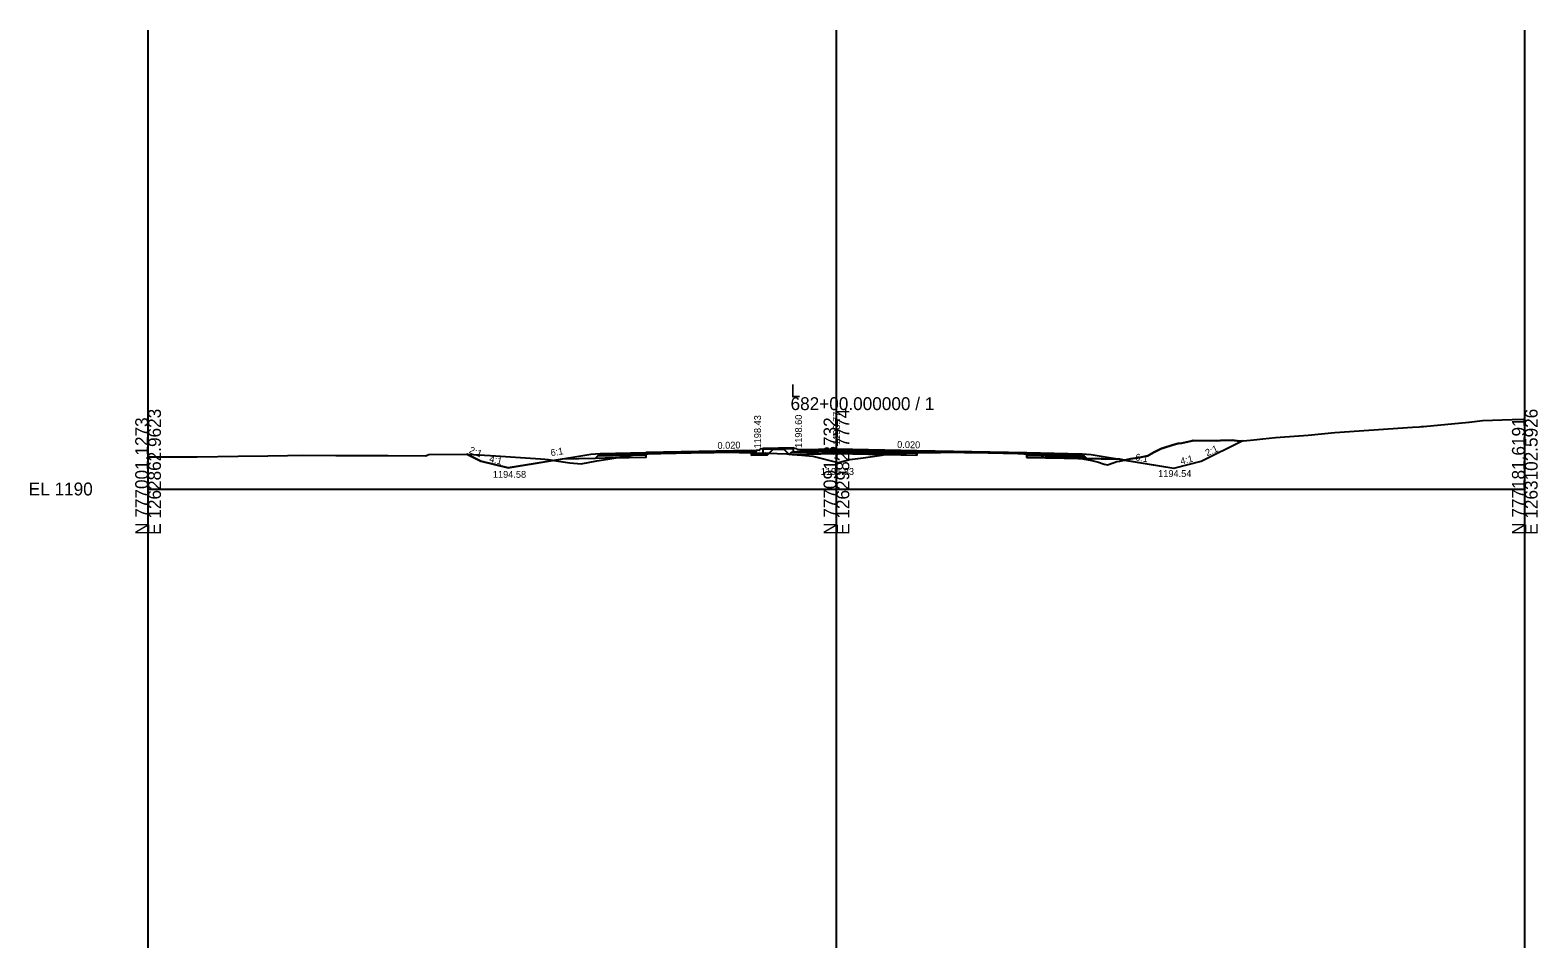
# Model space of a CAD drawing. Extents: x -41 to 1262860, y -100 to 777489.
# Drawn here: x 474.3 to 802.8, y 4065 to 4265 of the extents above; entities that cross this region are included whole.
import ezdxf

# ---------------------------------------------------------------- set-up
doc = ezdxf.new("R2010")
doc.units = 0
for name, color, linetype in [('Exist Cross Section Cell', 7, 'Continuous'), ('Exist XS Center Line Elevation Label', 7, 'Continuous'), ('Exist XS Ground Line', 7, 'Continuous'), ('Prop CMT Pvmt Course 1', 7, 'Continuous'), ('Prop CMT Pvmt Surface', 7, 'Continuous'), ('Prop CMT Shld Paved Course 1', 7, 'Continuous'), ('Prop CMT Shld Paved Course 2', 7, 'Continuous'), ('Prop CMT Shld Paved Course 4', 7, 'Continuous'), ('Prop CMT Subgrade Earthwork', 7, 'Continuous'), ('Prop Conc Curb and Gutter', 7, 'Continuous'), ('Prop Conc Island Cover', 7, 'Continuous'), ('Prop XS Ditch Standard Text', 7, 'Continuous'), ('Prop XS Earthwork Shape', 7, 'Continuous'), ('Prop XS Elevation Labels', 7, 'Continuous'), ('Prop XS Exc Vertical Line 1', 7, 'Continuous'), ('Prop XS Exc Vertical Line 2', 7, 'Continuous'), ('Prop XS Exc Vertical Line 3', 7, 'Continuous'), ('Prop XS Finish Grade', 7, 'Continuous'), ('Prop XS Hydro Elevations', 7, 'Continuous'), ('Prop XS SE Text', 7, 'Continuous'), ('Prop XS Side Slope Text', 7, 'Continuous'), ('Scratch_Level_4', 7, 'Continuous'), ('Scratch_Level_6', 7, 'Continuous')]:
    doc.layers.add(name, color=color, linetype=linetype)

msp = doc.modelspace()

# ---------------------------------------------------------------- linework, layer by layer
at = {"layer": 'Exist Cross Section Cell'}
for p, q in [((650, 4165), (650, 4185)), ((500, 4165), (650, 4165)), ((650, 4165), (800, 4165))]:
    msp.add_line(p, q, dxfattribs=at)
at = {"layer": 'Exist XS Ground Line'}
msp.add_lwpolyline([(500, 4172.04), (509.52, 4172.01), (510.05, 4172.01), (510.31, 4172.01), (510.7, 4172.02), (519.64, 4172.14), (526.09, 4172.23), (530.37, 4172.31), (533.6, 4172.34), (540.9, 4172.31), (551.94, 4172.31), (552.3, 4172.31), (560.54, 4172.22), (560.84, 4172.37), (561.2, 4172.55), (569.48, 4172.61), (569.78, 4172.6), (575.68, 4172.22), (585.55, 4171.57), (586.44, 4171.52), (587.2, 4171.4), (591.88, 4170.72), (594.34, 4170.49), (594.37, 4170.49), (594.39, 4170.49), (597.79, 4171.11), (600.18, 4171.51), (603.32, 4172.02), (603.77, 4172.09), (607.39, 4172.64), (608.94, 4172.75), (610.76, 4172.87), (617.6, 4172.95), (623.39, 4173.02), (628.79, 4172.93), (635.33, 4172.8), (637.07, 4172.72), (639.18, 4172.63), (642.49, 4172.36), (644.87, 4172.12), (650.29, 4170.76), (650.37, 4170.74), (650.42, 4170.75), (652.92, 4171.45), (655.81, 4171.81), (659.86, 4172.38), (661.46, 4172.63), (664.64, 4172.79), (665.3, 4172.82), (667.47, 4172.85), (677.88, 4173.02), (679.87, 4172.98), (689.55, 4172.78), (691.46, 4172.61), (692.25, 4172.52), (693.7, 4172.39), (698.26, 4172.02), (699.68, 4171.9), (703.23, 4171.63), (705.66, 4171.18), (707.1, 4170.84), (708.37, 4170.44), (709.04, 4170.24), (710.49, 4170.75), (711.1, 4170.97), (711.75, 4171.09), (714.07, 4171.6), (715.65, 4171.77), (717.85, 4172.24), (719.1, 4172.94), (720.85, 4173.84), (721.13, 4173.89), (723.35, 4174.65), (724.47, 4174.88), (725.27, 4175.01), (727.52, 4175.5), (727.74, 4175.54), (732.76, 4175.51), (733.72, 4175.58), (736.22, 4175.64), (737.82, 4175.46), (738.65, 4175.51), (740.26, 4175.65), (741.64, 4175.81), (742.9, 4175.95), (745.67, 4176.19), (752.8, 4176.72), (758.6, 4177.3), (775.54, 4178.47), (777.02, 4178.57), (777.52, 4178.59), (777.94, 4178.61), (787.78, 4179.58), (787.89, 4179.59), (790.75, 4179.94), (797.25, 4180.13), (800, 4180.24)], dxfattribs=at)
at = {"layer": 'Prop CMT Pvmt Course 1'}
for p, q in [((631.5, 4173.15), (632.5, 4173.17)), ((632.5, 4173.42), (632.5, 4173.17)), ((642.16, 4173.61), (642.16, 4173.36))]:
    msp.add_line(p, q, dxfattribs=at)
for points in [[(608.5, 4172.94), (608.5, 4172.69), (631.5, 4173.15), (631.5, 4173.15), (631.5, 4173.4), (631.5, 4173.4), (631.5, 4173.4), (608.5, 4172.94), (608.5, 4172.94)], [(642.16, 4173.36), (650, 4173.52), (667.5, 4173.17)], [(691.5, 4172.94), (691.5, 4172.69), (691.5, 4172.69), (667.5, 4173.17), (667.5, 4173.17), (667.5, 4173.42), (667.5, 4173.42), (667.5, 4173.42), (691.5, 4172.94), (691.5, 4172.94), (691.5, 4172.94)]]:
    msp.add_lwpolyline(points, dxfattribs=at)
at = {"layer": 'Prop CMT Pvmt Surface'}
for p, q in [((598.5, 4172.74), (608.5, 4172.94)), ((608.5, 4172.94), (631.5, 4173.4)), ((631.5, 4173.4), (632.5, 4173.42)), ((667.5, 4173.42), (691.5, 4172.94)), ((691.5, 4172.94), (703.5, 4172.7))]:
    msp.add_line(p, q, dxfattribs=at)
msp.add_lwpolyline([(642.16, 4173.61), (650, 4173.77), (667.5, 4173.42)], dxfattribs=at)
at = {"layer": 'Prop CMT Shld Paved Course 1'}
for p, q in [((598.24, 4172.48), (598.5, 4172.74)), ((608.5, 4172.69), (598.24, 4172.48)), ((604.5, 4172.86), (604.5, 4172.86)), ((608.5, 4172.94), (608.5, 4172.94)), ((608.5, 4172.94), (608.5, 4172.94)), ((608.5, 4172.94), (608.5, 4172.69)), ((608.5, 4172.69), (608.5, 4172.69)), ((691.5, 4172.94), (691.5, 4172.94)), ((691.5, 4172.94), (691.5, 4172.94)), ((691.5, 4172.94), (691.5, 4172.69)), ((691.5, 4172.69), (691.5, 4172.69)), ((691.5, 4172.69), (703.76, 4172.44)), ((695.5, 4172.86), (695.5, 4172.86)), ((703.76, 4172.44), (703.5, 4172.7))]:
    msp.add_line(p, q, dxfattribs=at)
at = {"layer": 'Prop CMT Shld Paved Course 2'}
for p, q in [((597.9, 4172.14), (598.24, 4172.48)), ((604.24, 4172.6), (604.24, 4172.6)), ((608.5, 4172.69), (608.5, 4172.69)), ((608.5, 4172.69), (608.5, 4172.69)), ((608.5, 4172.69), (608.5, 4172.35)), ((608.5, 4172.69), (608.94, 4172.69)), ((608.94, 4172.69), (608.5, 4172.69)), ((608.94, 4172.69), (610.76, 4172.73)), ((610.76, 4172.73), (608.94, 4172.69)), ((608.94, 4172.69), (608.94, 4172.69)), ((608.94, 4172.69), (608.94, 4172.69)), ((610.76, 4172.73), (617.6, 4172.87)), ((617.6, 4172.87), (610.76, 4172.73)), ((610.76, 4172.73), (610.76, 4172.73)), ((610.76, 4172.73), (610.76, 4172.73)), ((610.76, 4172.73), (610.76, 4172.73)), ((610.76, 4172.73), (610.76, 4172.73)), ((617.6, 4172.87), (623.39, 4172.98)), ((623.39, 4172.98), (617.6, 4172.87)), ((617.6, 4172.87), (617.6, 4172.87)), ((617.6, 4172.87), (617.6, 4172.87)), ((628.79, 4173.09), (623.39, 4172.98)), ((623.39, 4172.98), (624.26, 4173)), ((623.39, 4172.98), (623.39, 4172.98)), ((624.26, 4173), (628.79, 4172.93)), ((631.5, 4173.15), (628.79, 4173.09)), ((628.79, 4173.09), (628.79, 4173.09)), ((628.79, 4172.93), (628.79, 4172.93)), ((628.79, 4172.93), (631.5, 4172.87)), ((631.5, 4172.87), (631.5, 4173.15)), ((631.5, 4173.15), (631.5, 4173.15)), ((631.5, 4172.87), (631.5, 4172.81)), ((631.5, 4172.81), (632.5, 4172.83)), ((632.5, 4172.83), (632.5, 4173.17)), ((642.16, 4173.03), (642.16, 4173.36)), ((667.5, 4172.85), (667.5, 4173.17)), ((667.5, 4173.17), (667.5, 4173.17)), ((667.5, 4173.17), (667.5, 4173.17)), ((667.5, 4173.17), (677.88, 4172.96)), ((676.08, 4172.99), (667.5, 4172.85)), ((667.5, 4172.85), (667.5, 4172.83)), ((667.5, 4172.85), (667.5, 4172.85)), ((677.88, 4172.96), (676.08, 4172.99)), ((676.08, 4172.99), (676.08, 4172.99)), ((676.08, 4172.99), (676.08, 4172.99)), ((679.87, 4172.92), (677.88, 4172.96)), ((677.88, 4172.96), (677.88, 4172.96)), ((677.88, 4172.96), (679.87, 4172.92)), ((689.55, 4172.72), (679.87, 4172.92)), ((679.87, 4172.92), (679.87, 4172.92)), ((679.87, 4172.92), (679.87, 4172.92)), ((679.87, 4172.92), (679.87, 4172.92)), ((679.87, 4172.92), (679.87, 4172.92)), ((679.87, 4172.92), (679.87, 4172.92)), ((679.87, 4172.92), (679.87, 4172.92)), ((679.87, 4172.92), (689.55, 4172.72)), ((690.37, 4172.71), (689.55, 4172.72)), ((689.55, 4172.72), (689.55, 4172.72)), ((689.55, 4172.72), (689.55, 4172.72)), ((689.55, 4172.72), (689.55, 4172.72)), ((689.55, 4172.72), (689.55, 4172.72)), ((689.55, 4172.72), (691.46, 4172.69)), ((691.46, 4172.61), (690.37, 4172.71)), ((690.37, 4172.71), (690.37, 4172.71)), ((690.37, 4172.71), (690.37, 4172.71)), ((691.46, 4172.69), (691.5, 4172.69)), ((691.46, 4172.69), (691.46, 4172.69)), ((691.5, 4172.6), (691.46, 4172.61)), ((691.5, 4172.69), (691.5, 4172.69)), ((691.5, 4172.69), (691.5, 4172.69)), ((691.5, 4172.69), (691.5, 4172.35)), ((691.5, 4172.69), (691.5, 4172.69)), ((691.5, 4172.69), (691.5, 4172.6)), ((704.1, 4172.1), (703.76, 4172.44)), ((608.5, 4172.35), (597.9, 4172.14)), ((608.5, 4172.35), (608.5, 4172.35)), ((691.5, 4172.35), (691.5, 4172.35)), ((691.5, 4172.35), (704.1, 4172.1))]:
    msp.add_line(p, q, dxfattribs=at)
msp.add_lwpolyline([(642.16, 4173.03), (650, 4173.18), (667.5, 4172.83)], dxfattribs=at)
at = {"layer": 'Prop CMT Shld Paved Course 4'}
for p, q in [((631.5, 4172.81), (631.5, 4172.35)), ((631.5, 4172.35), (634.95, 4172.42)), ((632.5, 4172.83), (634.5, 4172.87)), ((634.5, 4172.87), (634.95, 4172.42)), ((640.16, 4172.99), (639.69, 4172.52)), ((642.16, 4172.57), (639.69, 4172.52)), ((642.16, 4173.03), (640.16, 4172.99)), ((667.5, 4172.83), (667.5, 4172.37)), ((597.44, 4171.67), (597.9, 4172.14)), ((608.5, 4171.89), (597.44, 4171.67)), ((603.4, 4172.25), (603.4, 4172.25)), ((603.9, 4172.26), (603.9, 4172.26)), ((608.5, 4172.35), (608.5, 4172.35)), ((608.5, 4172.35), (608.5, 4172.35)), ((608.5, 4172.35), (608.5, 4171.89)), ((691.5, 4172.35), (691.5, 4172.35)), ((691.5, 4172.35), (691.5, 4172.35)), ((691.5, 4172.35), (691.5, 4171.89)), ((691.5, 4171.89), (704.56, 4171.63)), ((704.56, 4171.63), (704.1, 4172.1))]:
    msp.add_line(p, q, dxfattribs=at)
msp.add_lwpolyline([(642.16, 4172.57), (650, 4172.72), (667.5, 4172.37)], dxfattribs=at)
at = {"layer": 'Prop CMT Subgrade Earthwork'}
for p, q in [((608.5, 4172.72), (608.5, 4171.89)), ((631.5, 4172.35), (631.5, 4172.87)), ((634.95, 4172.42), (631.5, 4172.35)), ((634.95, 4172.42), (636.18, 4173.65)), ((636.18, 4173.65), (638.51, 4173.7)), ((639.69, 4172.52), (638.51, 4173.7)), ((639.69, 4172.52), (650, 4172.72)), ((650, 4172.72), (667.5, 4172.37)), ((667.5, 4172.37), (667.5, 4172.85)), ((691.5, 4172.6), (691.5, 4171.89)), ((608.5, 4171.89), (590.22, 4171.53)), ((691.5, 4171.89), (711.78, 4171.49))]:
    msp.add_line(p, q, dxfattribs=at)
at = {"layer": 'Prop Conc Curb and Gutter'}
for p, q in [((633.19, 4173.43), (632.5, 4173.42)), ((632.5, 4172.83), (632.5, 4173.42)), ((632.5, 4172.83), (634, 4172.86)), ((633.25, 4173.51), (633.25, 4173.49)), ((634, 4173.86), (633.35, 4173.65)), ((634, 4172.86), (634, 4173.86)), ((640.66, 4173.99), (641.3, 4173.8)), ((640.66, 4173), (640.66, 4173.99)), ((642.16, 4173.03), (640.66, 4173)), ((641.41, 4173.67), (641.41, 4173.66)), ((641.47, 4173.6), (642.16, 4173.61)), ((642.16, 4173.03), (642.16, 4173.61))]:
    msp.add_line(p, q, dxfattribs=at)
for centre, radius, start, end in [((633.19, 4173.49), 0.0625, 271.1458, 360), ((633.4, 4173.51), 0.146, 108.435, 180), ((641.26, 4173.66), 0.146, 2.2915, 73.8566), ((641.47, 4173.66), 0.0625, 182.2915, 271.1458)]:
    msp.add_arc(centre, radius, start, end, dxfattribs=at)
at = {"layer": 'Prop Conc Island Cover'}
for p, q in [((640.66, 4173.99), (634, 4173.86)), ((640.66, 4173.74), (634, 4173.61))]:
    msp.add_line(p, q, dxfattribs=at)
at = {"layer": 'Prop XS Earthwork Shape'}
for points in [[(569.78, 4172.6), (575.68, 4172.22), (585.55, 4171.57), (586.44, 4171.52), (587.2, 4171.4), (588.41, 4171.23), (578.5, 4169.58), (572.5, 4171.08), (569.43, 4172.61), (569.48, 4172.61)], [(603.77, 4172.09), (607.39, 4172.64), (608.5, 4172.72), (608.5, 4171.89), (601.71, 4171.76), (603.32, 4172.02)], [(634.95, 4172.42), (631.5, 4172.35), (631.5, 4172.87), (635.33, 4172.8)], [(639.18, 4172.63), (639.62, 4172.59), (638.51, 4173.7), (636.18, 4173.65), (635.33, 4172.8), (637.07, 4172.72)], [(639.62, 4172.59), (640.38, 4172.53), (639.69, 4172.52)], [(659.86, 4172.38), (660.72, 4172.51), (650, 4172.72), (640.38, 4172.53), (642.49, 4172.36), (644.87, 4172.12), (650.29, 4170.76), (650.37, 4170.74), (650.42, 4170.75), (652.92, 4171.45), (655.81, 4171.81)], [(660.72, 4172.51), (667.5, 4172.37), (667.5, 4172.85), (667.47, 4172.85), (665.3, 4172.82), (664.64, 4172.79), (661.46, 4172.63)], [(698.26, 4172.02), (699.68, 4171.9), (702.65, 4171.67), (691.5, 4171.89), (691.5, 4172.6), (692.25, 4172.52), (693.7, 4172.39)], [(712.79, 4171.32), (723.5, 4169.54), (729.5, 4171.04), (738.42, 4175.49), (737.82, 4175.46), (736.22, 4175.64), (733.72, 4175.58), (732.76, 4175.51), (727.74, 4175.54), (727.52, 4175.5), (725.27, 4175.01), (724.47, 4174.88), (723.35, 4174.65), (721.13, 4173.89), (720.85, 4173.84), (719.1, 4172.94), (717.85, 4172.24), (715.65, 4171.77), (714.07, 4171.6)], [(600.18, 4171.51), (601.71, 4171.76), (597.44, 4171.67), (590.22, 4171.53), (588.41, 4171.23), (591.88, 4170.72), (594.34, 4170.49), (594.37, 4170.49), (594.39, 4170.49), (597.79, 4171.11)], [(711.75, 4171.09), (712.79, 4171.32), (711.78, 4171.49), (704.56, 4171.63), (702.65, 4171.67), (703.23, 4171.63), (705.66, 4171.18), (707.1, 4170.84), (708.37, 4170.44), (709.04, 4170.24), (710.49, 4170.75), (711.1, 4170.97)]]:
    msp.add_lwpolyline(points, close=True, dxfattribs=at)
at = {"layer": 'Prop XS Exc Vertical Line 1'}
msp.add_line((500, 4065), (500, 4265), dxfattribs=at)
at = {"layer": 'Prop XS Exc Vertical Line 2'}
msp.add_line((650, 4065), (650, 4265), dxfattribs=at)
at = {"layer": 'Prop XS Exc Vertical Line 3'}
msp.add_line((800, 4065), (800, 4265), dxfattribs=at)
at = {"layer": 'Prop XS Finish Grade'}
for p, q in [((569.43, 4172.61), (572.5, 4171.08)), ((578.5, 4169.58), (596.5, 4172.58)), ((596.5, 4172.58), (598.5, 4172.74)), ((597.44, 4171.67), (598.5, 4172.74)), ((703.5, 4172.7), (705.5, 4172.54)), ((703.5, 4172.7), (704.56, 4171.63)), ((705.5, 4172.54), (723.5, 4169.54)), ((729.5, 4171.04), (738.42, 4175.49)), ((572.5, 4171.08), (578.5, 4169.58)), ((723.5, 4169.54), (729.5, 4171.04))]:
    msp.add_line(p, q, dxfattribs=at)
at = {"layer": 'Scratch_Level_4'}
msp.add_line((800, 4065), (800, 4265), dxfattribs=at)
at = {"layer": 'Scratch_Level_6'}
msp.add_line((500, 4065), (500, 4265), dxfattribs=at)

# ---------------------------------------------------------------- texts
at = {"layer": 'Exist Cross Section Cell'}
for s, p in [('L', (640, 4185)), ('682+00.000000 / 1', (640, 4182.2)), ('EL 1190', (474, 4163.6))]:
    msp.add_text(s, height=2.8, dxfattribs=at).set_placement(p)
for s, p in [('E 1262862.9623', (502.8, 4155)), ('E 1262982.7774', (652.8, 4155)), ('E 1263102.5926', (802.8, 4155)), ('N 777001.1273', (500, 4155)), ('N 777091.3732', (650, 4155)), ('N 777181.6191', (800, 4155))]:
    msp.add_text(s, height=2.8, rotation=90, dxfattribs=at).set_placement(p)
at = {"layer": 'Exist XS Center Line Elevation Label'}
msp.add_text('1195.83', height=1.5, dxfattribs=at).set_placement((646.58, 4168.08))
at = {"layer": 'Prop XS Ditch Standard Text'}
for s, p in [('1194.54', (720.1, 4167.62)), ('1194.58', (575.13, 4167.44))]:
    msp.add_text(s, height=1.5, dxfattribs=at).set_placement(p)
at = {"layer": 'Prop XS Elevation Labels'}
for s, p in [('1198.43', (633.57, 4173.84)), ('1198.60', (642.49, 4173.96))]:
    msp.add_text(s, height=1.5, rotation=90, dxfattribs=at).set_placement(p)
at = {"layer": 'Prop XS Hydro Elevations'}
msp.add_text('1198.77', height=1.5, rotation=90, dxfattribs=at).set_placement((650.76, 4174.59))
at = {"layer": 'Prop XS SE Text'}
for rotation, p in [(1.1458, (624.09, 4173.74)), (358.8542, (663.22, 4173.96))]:
    msp.add_text('0.020', height=1.5, rotation=rotation, dxfattribs=at).set_placement(p)
at = {"layer": 'Prop XS Side Slope Text'}
for s, rotation, p in [('2:1', 338.2726, (569.82, 4172.92)), ('6:1', 9.4623, (587.83, 4172.13)), ('6:1', 350.5377, (715.03, 4171.27)), ('2:1', 24.7387, (730.78, 4172.1)), ('4:1', 345.9638, (574.25, 4170.95)), ('4:1', 14.0362, (725.13, 4170.29))]:
    msp.add_text(s, height=1.5, rotation=rotation, dxfattribs=at).set_placement(p)

doc.saveas('drawing.dxf')
